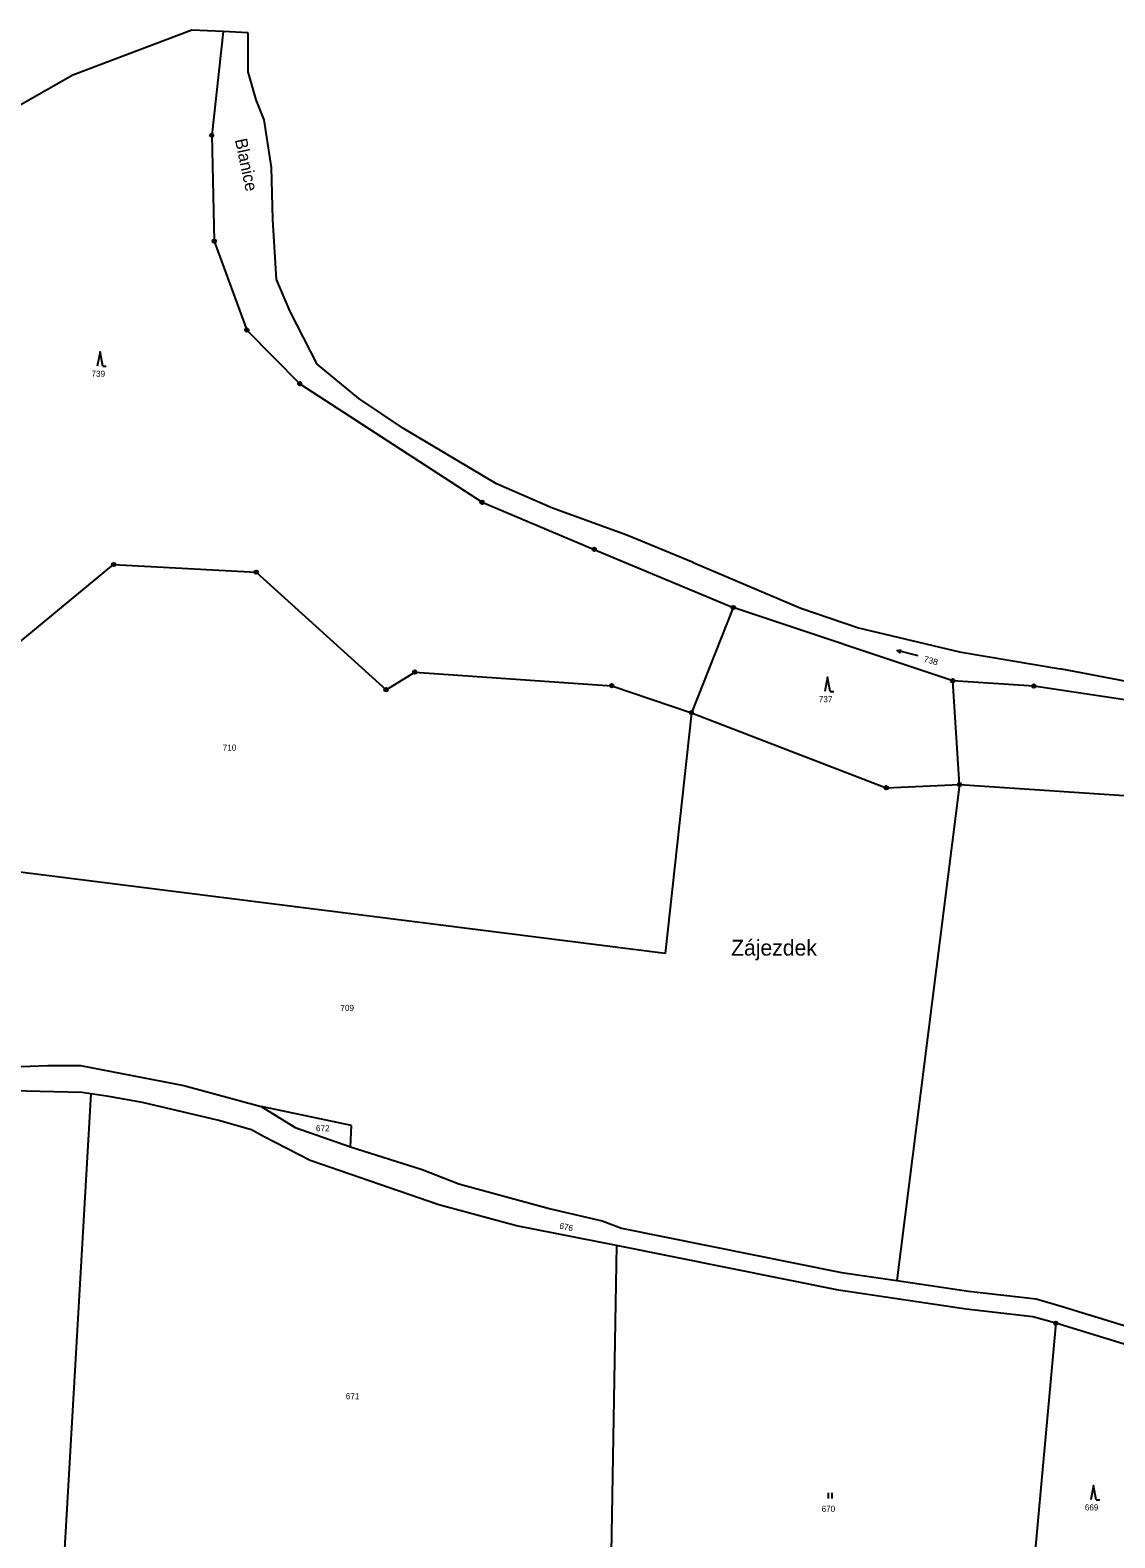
# Model space of a CAD drawing. Extents: x -719614 to -717765, y -1095834 to -1093862.
# Drawn here: x -718737.1 to -718435.2, y -1094701.4 to -1094281.8 of the extents above; entities that cross this region are included whole.
import ezdxf
from ezdxf.enums import TextEntityAlignment as Align

# ---------------------------------------------------------------- set-up
doc = ezdxf.new("R2010")
doc.units = 0
doc.header["$LTSCALE"] = 0.68
for name, color, linetype, lineweight in [('1', 7, 'Continuous', 25), ('3', 7, 'Continuous', 25), ('8', 7, 'Continuous', 25)]:
    doc.layers.add(name, color=color, linetype=linetype, lineweight=lineweight)
doc.layers.add('2', color=7, linetype='Continuous')
doc.layers.add('7', color=7, linetype='Continuous')

msp = doc.modelspace()

# ---------------------------------------------------------------- linework, layer by layer
at = {"layer": '1'}
for p, q in [((-718692.14, -1094281.8), (-718725.22, -1094294.33)), ((-718683.36, -1094282.21), (-718692.14, -1094281.8)), ((-718683.36, -1094282.21), (-718686.6, -1094311.06)), ((-718676.42, -1094282.53), (-718683.36, -1094282.21)), ((-718725.22, -1094294.33), (-718760.81, -1094314.57)), ((-718686.6, -1094311.06), (-718685.88, -1094340.53)), ((-718685.88, -1094340.53), (-718676.84, -1094365.26)), ((-718657.26, -1094374.78), (-718664.72, -1094360.14)), ((-718676.84, -1094365.26), (-718662.1, -1094380.18)), ((-718662.1, -1094380.18), (-718611.36, -1094413.17)), ((-718607.34, -1094408.06), (-718633.17, -1094392.64)), ((-718611.36, -1094413.17), (-718580.16, -1094426.28)), ((-718580.16, -1094426.28), (-718541.45, -1094442.47)), ((-718764.5, -1094472.16), (-718713.88, -1094430.51)), ((-718713.88, -1094430.51), (-718674.19, -1094432.63)), ((-718552.62, -1094429.92), (-718522.61, -1094442.67)), ((-718674.19, -1094432.63), (-718638.07, -1094465.36)), ((-718541.45, -1094442.47), (-718553.1, -1094471.75)), ((-718480.35, -1094462.85), (-718541.45, -1094442.47)), ((-718522.61, -1094442.67), (-718506.62, -1094448.08)), ((-718506.62, -1094448.08), (-718478.52, -1094454.84)), ((-718478.52, -1094454.84), (-718450.5, -1094459.53)), ((-718638.07, -1094465.36), (-718630.09, -1094460.45)), ((-718630.09, -1094460.45), (-718575.26, -1094464.22)), ((-718417.41, -1094465.85), (-718450.5, -1094459.53)), ((-718575.26, -1094464.22), (-718553.1, -1094471.75)), ((-718478.47, -1094491.73), (-718480.35, -1094462.85)), ((-718457.79, -1094464.33), (-718480.35, -1094462.85)), ((-718394.47, -1094473.83), (-718457.79, -1094464.33)), ((-718553.1, -1094471.75), (-718560.43, -1094538.75)), ((-718553.1, -1094471.75), (-718498.85, -1094492.63)), ((-718498.85, -1094492.63), (-718478.47, -1094491.73)), ((-718478.47, -1094491.73), (-718495.94, -1094629.77)), ((-718478.47, -1094491.73), (-718373.34, -1094498.79)), ((-718631.67, -1094529.78), (-718811.16, -1094507.18)), ((-718560.43, -1094538.75), (-718631.67, -1094529.78)), ((-718742, -1094570.33), (-718732.24, -1094569.91)), ((-718732.24, -1094569.91), (-718723.09, -1094569.95)), ((-718723.09, -1094569.95), (-718694.34, -1094575.51)), ((-718722.78, -1094577.46), (-718742.11, -1094576.99)), ((-718720.2, -1094577.83), (-718728.32, -1094718.2)), ((-718720.2, -1094577.83), (-718722.78, -1094577.46)), ((-718715.21, -1094578.54), (-718720.2, -1094577.83)), ((-718694.34, -1094575.51), (-718672.87, -1094581.33)), ((-718705.86, -1094580.26), (-718715.21, -1094578.54)), ((-718684.94, -1094585.11), (-718705.86, -1094580.26)), ((-718647.7, -1094586.65), (-718672.87, -1094581.33)), ((-718672.87, -1094581.33), (-718663.35, -1094587.13)), ((-718675.48, -1094587.84), (-718684.94, -1094585.11)), ((-718672.2, -1094589.64), (-718675.48, -1094587.84)), ((-718659.19, -1094596.33), (-718672.2, -1094589.64)), ((-718663.35, -1094587.13), (-718647.98, -1094592.58)), ((-718647.98, -1094592.58), (-718647.7, -1094586.65)), ((-718647.98, -1094592.58), (-718628.01, -1094598.82)), ((-718623.42, -1094608.66), (-718659.19, -1094596.33)), ((-718628.01, -1094598.82), (-718617.77, -1094602.84)), ((-718617.77, -1094602.84), (-718592.29, -1094609.79)), ((-718601.81, -1094614.53), (-718623.42, -1094608.66)), ((-718592.29, -1094609.79), (-718577.89, -1094613.12)), ((-718573.91, -1094620.01), (-718601.81, -1094614.53)), ((-718577.89, -1094613.12), (-718572.51, -1094615.19)), ((-718572.51, -1094615.19), (-718511.3, -1094627.49)), ((-718573.91, -1094620.01), (-718575.68, -1094721.84)), ((-718512.16, -1094632.42), (-718573.91, -1094620.01)), ((-718511.3, -1094627.49), (-718495.94, -1094629.77)), ((-718476.61, -1094637.7), (-718512.16, -1094632.42)), ((-718495.94, -1094629.77), (-718475.96, -1094632.74)), ((-718475.96, -1094632.74), (-718457.1, -1094634.9)), ((-718457.1, -1094634.9), (-718450.16, -1094636.86)), ((-718450.16, -1094636.86), (-718416.62, -1094647.19)), ((-718458.07, -1094639.82), (-718476.61, -1094637.7)), ((-718451.67, -1094641.63), (-718458.07, -1094639.82)), ((-718451.67, -1094641.63), (-718460.98, -1094743.29)), ((-718418.32, -1094651.9), (-718451.67, -1094641.63))]:
    msp.add_line(p, q, dxfattribs=at)
for points in [[(-718672.01, -1094306.75), (-718674.25, -1094301.22), (-718676.42, -1094293.37), (-718676.42, -1094282.53)], [(-718664.72, -1094360.14), (-718668.53, -1094351.15), (-718669.59, -1094334.48), (-718669.98, -1094320.01), (-718672.01, -1094306.75)], [(-718633.17, -1094392.64), (-718645.6, -1094384.32), (-718657.26, -1094374.78)], [(-718552.62, -1094429.92), (-718571.06, -1094422.3), (-718591.72, -1094414.84), (-718607.34, -1094408.06)]]:
    msp.add_lwpolyline(points, dxfattribs=at)
at = {"layer": '3'}
for p, q in [((-718716.93, -1094375.28), (-718715.934, -1094375.28)), ((-718495.815, -1094454.452), (-718494.746, -1094454.202)), ((-718514.47, -1094465.85), (-718513.474, -1094465.85)), ((-718514.961, -1094690.38), (-718514.961, -1094688.88)), ((-718513.96, -1094690.38), (-718513.96, -1094688.88)), ((-718440.42, -1094690.76), (-718439.424, -1094690.76))]:
    msp.add_line(p, q, dxfattribs=at)
for points in [[(-718716.93, -1094375.28), (-718717.68, -1094371.28), (-718718.43, -1094375.28)], [(-718489.994, -1094455.903), (-718495.815, -1094454.452), (-718494.989, -1094455.175)], [(-718514.47, -1094465.85), (-718515.22, -1094461.85), (-718515.97, -1094465.85)], [(-718440.42, -1094690.76), (-718441.17, -1094686.76), (-718441.92, -1094690.76)]]:
    msp.add_lwpolyline(points, dxfattribs=at)
at = {"layer": '8'}
for centre, radius in [((-718686.6, -1094311.0599), 0.5), ((-718686.6, -1094311.0599), 0.0303), ((-718685.88, -1094340.5299), 0.5), ((-718685.88, -1094340.5299), 0.0303), ((-718676.84, -1094365.2599), 0.5), ((-718676.84, -1094365.2599), 0.0303), ((-718662.1, -1094380.1799), 0.5), ((-718662.1, -1094380.1799), 0.0303), ((-718611.36, -1094413.1699), 0.5), ((-718611.36, -1094413.1699), 0.0303), ((-718580.16, -1094426.2799), 0.5), ((-718580.16, -1094426.2799), 0.0303), ((-718713.88, -1094430.5099), 0.5), ((-718713.88, -1094430.5099), 0.0303), ((-718674.19, -1094432.6299), 0.5), ((-718674.19, -1094432.6299), 0.0303), ((-718541.45, -1094442.4699), 0.5), ((-718541.45, -1094442.4699), 0.0303), ((-718630.09, -1094460.4499), 0.5), ((-718630.09, -1094460.4499), 0.0303), ((-718638.07, -1094465.3599), 0.5), ((-718575.26, -1094464.2199), 0.5), ((-718575.26, -1094464.2199), 0.0303), ((-718480.35, -1094462.8499), 0.5), ((-718480.35, -1094462.8499), 0.0303), ((-718457.79, -1094464.3299), 0.5), ((-718457.79, -1094464.3299), 0.0303), ((-718638.07, -1094465.3599), 0.0303), ((-718553.1, -1094471.7499), 0.5), ((-718553.1, -1094471.7499), 0.0303), ((-718498.85, -1094492.6299), 0.5), ((-718498.85, -1094492.6299), 0.0303), ((-718478.47, -1094491.7299), 0.5), ((-718478.47, -1094491.7299), 0.0303), ((-718451.67, -1094641.6299), 0.5), ((-718451.67, -1094641.6299), 0.0303)]:
    msp.add_circle(centre, radius, dxfattribs=at)

# ---------------------------------------------------------------- texts
at = {"layer": '2'}
for s, p in [('739', (-718718.159, -1094378.262)), ('737', (-718515.739, -1094468.832)), ('710', (-718681.629, -1094482.302)), ('709', (-718648.899, -1094554.742)), ('672', (-718655.679, -1094588.242)), ('671', (-718647.379, -1094662.802)), ('670', (-718514.959, -1094694.142)), ('669', (-718441.699, -1094693.742))]:
    msp.add_text(s, height=1.7, dxfattribs=at).set_placement(p, align=Align.CENTER)
at = {"layer": '2', "width": 1.05}
msp.add_text('738', height=1.7, rotation=345, dxfattribs=at).set_placement((-718486.65, -1094458.0583), align=Align.CENTER)
at = {"layer": '2'}
msp.add_text('676', height=1.7, rotation=348, dxfattribs=at).set_placement((-718588.0867, -1094615.6832), align=Align.CENTER)
at = {"layer": '7'}
msp.add_text('Blanice', height=3.4, rotation=282, dxfattribs=at).set_placement((-718678.6026, -1094319.6066), align=Align.CENTER)
msp.add_text('Zájezdek', height=4.4, dxfattribs=at).set_placement((-718542.04, -1094539.34))

doc.saveas('drawing.dxf')
